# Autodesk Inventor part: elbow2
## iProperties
Shininess: 64.0
Length Units: 11269
Angle Units: 11279
Time Units: 11290
Mass Units: 11283
Length Display Precision: 3
Angle Display Precision: 2
Compacted: True
Part Number: elbow2
Document SubType Name: Modeling
Created: 2003-07
Designer: JB
Density: 0.0
Volumn: 0.0
Area: 0.0
PropertySet Name: Model Information
Control State: 0
Master: False
Checked Out: False
Author: JB
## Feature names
1. Sweep2
